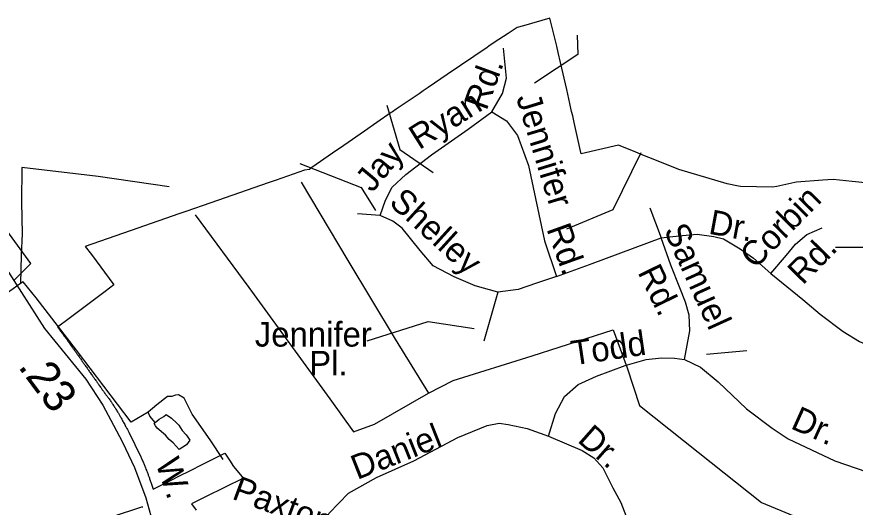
# Model space of a CAD drawing. Extents: x 2315291 to 2336543, y 597177 to 615230.
# Drawn here: x 2318553 to 2321792, y 600720 to 602614 of the extents above; entities that cross this region are included whole.
import ezdxf

# ---------------------------------------------------------------- set-up
doc = ezdxf.new("R2010")
doc.units = 0
for name, color, linetype in [('Exist Boundary Political City Limit New', 7, 'Continuous'), ('Exist Boundary Political Urban Extension UEB', 7, 'Continuous'), ('Exist Hydrographic Misc Water Feature', 7, 'Continuous'), ('Exist Road Non-System Type 51', 7, 'Continuous'), ('Exist Road Non-System Type 51 Label', 7, 'Continuous'), ('Exist Road Secondary Mileage Hundredths English Label', 7, 'Continuous'), ('Exist Road Secondary Type 51 Attributed', 7, 'Continuous'), ('Exist Road Secondary Type 51 Label', 7, 'Continuous'), ('Map Preparation Boundary City Limit Buffer Line', 7, 'Continuous')]:
    doc.layers.add(name, color=color, linetype=linetype)

msp = doc.modelspace()

# ---------------------------------------------------------------- linework, layer by layer
at = {"layer": 'Exist Boundary Political City Limit New'}
for points in [[(2320677.5, 602333.2), (2320653.5, 602437), (2320644.2, 602476), (2320638.8, 602500), (2320631.5, 602530.6), (2320612.8, 602608.9), (2320510, 602579.2), (2320486, 602572.2), (2320451.5, 602549.4), (2320397.5, 602513.8), (2320377, 602500), (2320370.2, 602495.4), (2320216.2, 602391.1), (2320142.2, 602340.3), (2320123.2, 602327.2), (2320107.5, 602316.6), (2320018.8, 602256.4), (2320005.2, 602247.1), (2320000, 602243.4), (2319944.2, 602204.8), (2319896, 602171.5), (2319816.2, 602116.2), (2319773.2, 602086.5), (2319693.5, 602031.3), (2319683.8, 602024.5), (2319664.2, 602021.1), (2319555.2, 601983.2), (2319524.8, 601972.6), (2319302.8, 601895.4), (2319206.2, 601861.8), (2319179.5, 601852.5), (2319021, 601797.4), (2318817.8, 601726.8), (2318841.5, 601695.1), (2318928.5, 601578.3), (2318894.8, 601553.1), (2318755.8, 601448.9), (2318711.2, 601415.7), (2318712, 601414.7), (2318713.8, 601412.2), (2318715.5, 601409.9), (2318718, 601406.6), (2318720.2, 601403.4), (2318722.8, 601400.2), (2318725, 601396.9), (2318727.5, 601393.8), (2318729.8, 601390.5), (2318732.2, 601387.2), (2318734.5, 601384), (2318736.8, 601380.8), (2318738.5, 601378.4), (2318740.2, 601375.9), (2318742.8, 601372.7), (2318745, 601369.4), (2318747.5, 601366.2), (2318749.2, 601363.8), (2318751, 601361.3), (2318752.8, 601358.9), (2318754.5, 601356.4), (2318756.8, 601353.2), (2318761.2, 601346.7), (2318763.8, 601343.4), (2318768.2, 601336.9), (2318770, 601334.5), (2318771.8, 601332), (2318773.5, 601329.6), (2318775.2, 601327.1), (2318777, 601324.7), (2318778.8, 601322.2), (2318780.5, 601319.8), (2318781.2, 601318.8), (2318781.8, 601318.2), (2318782.5, 601316.9), (2318784, 601314.9), (2318785.8, 601312.5), (2318787.5, 601310), (2318789.2, 601307.6), (2318791.5, 601304.3), (2318793.8, 601301), (2318795.5, 601298.6), (2318797.2, 601296.1), (2318799, 601293.7), (2318800.8, 601291.2), (2318803, 601288), (2318804.8, 601285.5), (2318806.5, 601283.1), (2318808.8, 601279.8), (2318810.5, 601277.3), (2318812.2, 601274.9), (2318814, 601272.4), (2318815.8, 601270), (2318818, 601266.8), (2318820.2, 601263.4), (2318822.5, 601260.2), (2318825, 601256.9), (2318827.2, 601253.6), (2318829, 601251.2), (2318830.8, 601248.8)], [(2321905.8, 601965.2), (2321779.8, 601978), (2321707, 601985.4), (2321686.5, 601983.8), (2321666, 601982.3), (2321565, 601974.6), (2321558, 601974.1), (2321488.5, 601958.8), (2321472, 601955.1), (2321348, 601957.8), (2321341, 601959.1), (2321297.5, 601968.4), (2321109.8, 602023.9), (2321018.2, 602060.7), (2320971.2, 602079.6), (2320943.8, 602090.6), (2320876.8, 602117.6), (2320733.5, 602083.8), (2320732.5, 602089.1), (2320706.2, 602205), (2320700.5, 602230.9), (2320696.5, 602248.5), (2320689.8, 602278.9), (2320677.5, 602333.2)], [(2318830.8, 601248.8), (2318833, 601245.5), (2318834.8, 601243.1)], [(2318834.8, 601243.1), (2318836.5, 601240.6), (2318841, 601234.1), (2318843.5, 601230.8), (2318845.8, 601227.5), (2318847.5, 601225.1), (2318849.2, 601222.6), (2318851, 601220.2), (2318852.5, 601217.7), (2318854.2, 601215.2), (2318856, 601212.8), (2318858.5, 601209.6), (2318860.8, 601206.2), (2318862.5, 601203.8), (2318864.2, 601201.4), (2318866, 601198.9), (2318867.8, 601196.5), (2318870, 601193.2), (2318872.2, 601189.9), (2318874.5, 601186.7), (2318877, 601183.4), (2318879.2, 601180.2), (2318883.8, 601173.7), (2318886.2, 601170.4), (2318888, 601167.9), (2318889.8, 601165.5), (2318892, 601162.2), (2318894.2, 601159.1), (2318896.2, 601156.6), (2318898, 601154.2), (2318900.5, 601151.1), (2318902.2, 601148.7), (2318904, 601146.3), (2318906.5, 601143.1), (2318908.2, 601140.8), (2318910, 601138.3), (2318912.5, 601135.1), (2318914.8, 601131.8), (2318917, 601128.5), (2318919.2, 601125.2), (2318921, 601122.7), (2318922.2, 601120.6), (2318923, 601119.4), (2318924.8, 601116.9), (2318927, 601113.2), (2318929.2, 601110), (2318931.2, 601106.8), (2318933, 601104.2), (2318934.5, 601101.4), (2318936.5, 601098.3), (2318938.8, 601094.9), (2318940.5, 601091.9), (2318942.8, 601088.1), (2318944.2, 601085.4), (2318945.8, 601082.9), (2318947.2, 601080.2), (2318948.8, 601077.7), (2318950.2, 601075.1), (2318951.8, 601072.5), (2318953.2, 601069.9), (2318954.8, 601067.1), (2318956.8, 601063.8), (2318958.8, 601060.2), (2318960.5, 601056.8), (2318962.2, 601053.5), (2318964.5, 601049.8), (2318966.2, 601046.4), (2318968.2, 601042.7), (2318970.2, 601039.2), (2318972, 601035.9), (2318974, 601032.1), (2318976, 601028.6), (2318977.2, 601026), (2318978.8, 601023.5), (2318980.5, 601019.8), (2318982, 601017.2), (2318983.2, 601014.5), (2318985, 601011.6), (2318985.8, 601009.9), (2319032, 600914.8), (2319033.5, 600911.4), (2319035, 600907.9), (2319036.2, 600904.9), (2319037.8, 600901.9), (2319039.2, 600898.5), (2319041, 600894.7), (2319042.5, 600891.2), (2319043.8, 600888.4), (2319045, 600885.4), (2319046.5, 600882), (2319048, 600878.3), (2319049.2, 600875.6), (2319051, 600871.3), (2319052.5, 600867.2), (2319054.2, 600863.4), (2319054.5, 600862.5), (2319054.8, 600861.6), (2319056, 600858.9)], [(2319056, 600858.9), (2319057, 600856.1), (2319058.2, 600852.4), (2319059.5, 600849.5), (2319060.5, 600846.7), (2319061.5, 600843.8), (2319062.5, 600841), (2319063.5, 600838.2), (2319064.5, 600835.4), (2319065.5, 600832.5), (2319066.5, 600829.7), (2319067.8, 600825.7), (2319068.2, 600824.6), (2319069, 600822.1), (2319070, 600819.3), (2319071, 600816.4), (2319072.2, 600812.6), (2319073.2, 600809.2), (2319074.8, 600805.1), (2319076, 600801.1), (2319077.2, 600797.3), (2319078.5, 600793.6), (2319079.8, 600789.8), (2319155.2, 600827.4), (2319179.2, 600839.6), (2319182, 600841.1), (2319221.8, 600860.9), (2319271.5, 600885.9), (2319356.8, 600928.6), (2319375.2, 600900.9), (2319391, 600877.7), (2319424.2, 600837.7), (2319428.8, 600832.6), (2319281.8, 600759.5), (2319241.2, 600739.5), (2319228.8, 600733.2), (2319246.5, 600708.2)], [(2319039.5, 600718.5), (2319038.8, 600721.7), (2318179, 600438.4)]]:
    msp.add_lwpolyline(points, dxfattribs=at)
at = {"layer": 'Exist Boundary Political Urban Extension UEB'}
msp.add_lwpolyline([(2318542.1, 601594.9), (2318607.6, 601660.5), (2318494.4, 601816.2), (2318437.7, 601929.5), (2318395.3, 602099.4), (2318366.9, 602297.6), (2318423.6, 602453.3), (2318451.9, 602665.7), (2318494.4, 602906.3), (2318466, 603090.4), (2318423.6, 603175.3), (2318692.6, 603345.2), (2318735.1, 603387.7), (2318848.4, 603600.1), (2319238.3, 604375.7)], dxfattribs=at)
at = {"layer": 'Exist Hydrographic Misc Water Feature'}
for points in [[(2319141.7, 601957.6), (2318867.4, 601996.5), (2318573.5, 602031.3), (2318572.3, 601897.3), (2318573.7, 601775.4), (2318570.9, 601693.6), (2318568.2, 601583.2)], [(2319651.3, 601975), (2319832.1, 601672.8), (2320015.5, 601369.1), (2320143.8, 601160.7)], [(2319243, 601848.6), (2319449.7, 601568.9), (2319762, 601138.3), (2319853.5, 601011.4), (2319935.3, 601040.5), (2320074.1, 601119.7), (2320143.8, 601160.7)], [(2318568.2, 601583.2), (2318540.1, 601563.1), (2318496.4, 601532.8), (2318492.3, 601528.5)], [(2319060.9, 601086.9), (2318995.5, 601048.5), (2318784.5, 601326), (2318628.7, 601528.3), (2318577.6, 601589.5), (2318568.2, 601583.2)], [(2320143.8, 601160.7), (2320239.2, 601209.6), (2320544.1, 601304.9), (2320856.8, 601404.2), (2320910.3, 601258.7), (2320957.9, 601113.2), (2321185.3, 600931.8), (2321429.5, 600738.5), (2321842.9, 600567.2), (2322346.9, 600362.8), (2322643, 600741.7), (2323035.1, 601251.6), (2323257.7, 601549.8)], [(2319350.7, 600904.2), (2319299.8, 600979.6), (2319230.9, 601078.8), (2319200, 601140.6), (2319178, 601154), (2319166.3, 601152.2), (2319152.4, 601147.8), (2319136.2, 601147.8), (2319094.8, 601115.5), (2319060.9, 601086.9)], [(2319087.6, 601047.2), (2319067.3, 601070.9), (2319060.9, 601086.9)], [(2319087.6, 601047.2), (2319103.2, 601059.4), (2319121, 601069.7), (2319130.9, 601077.6), (2319151.6, 601063.9), (2319171.7, 601044.3), (2319179.3, 601036.2), (2319191.8, 601016.5), (2319207.8, 600998.7), (2319214.1, 600990.8), (2319221.9, 600978.7), (2319208.4, 600960.5), (2319180.7, 600942.3), (2319158.1, 600968), (2319141.7, 600981.9), (2319127.8, 600997.8), (2319095.8, 601025.3), (2319089.4, 601033.5), (2319083.5, 601043.3), (2319087.6, 601047.2)]]:
    msp.add_lwpolyline(points, dxfattribs=at)
at = {"layer": 'Exist Road Non-System Type 51'}
for p, q in [((2320998.9, 601876.1), (2321042.1, 601759.8)), ((2319956.7, 601846.7), (2319869.5, 601852.8)), ((2320410.9, 601550.5), (2320357.2, 601360.7))]:
    msp.add_line(p, q, dxfattribs=at)
for points in [[(2320388.6, 602246.4), (2320429.1, 602317.4), (2320445.3, 602376.3), (2320433.2, 602491.9)], [(2319956.7, 601846.7), (2319977, 601905.6), (2320003.3, 601956.3), (2320056, 602005), (2320155.4, 602080.1), (2320297.3, 602179.5), (2320388.6, 602246.4)], [(2320388.6, 602246.4), (2320445.3, 602211.9), (2320487.9, 602155.1), (2320529.8, 602039.8), (2320556.9, 601911.3), (2320592, 601749), (2320638, 601611)], [(2320410.9, 601550.5), (2320323.7, 601574.9), (2320242.6, 601609.4), (2320161.5, 601652), (2320110.8, 601710.8), (2320041.8, 601798), (2320005.4, 601824.4), (2319956.7, 601846.7)], [(2321465.2, 601622.5), (2321526.1, 601693.5), (2321560.5, 601736.2), (2321605.1, 601772.7), (2321663.9, 601799.1)], [(2321042.1, 601759.8), (2321086.7, 601765.2), (2321124.6, 601768.6), (2321181.4, 601774.7), (2321246.2, 601764.6), (2321282.7, 601756.4), (2321347.6, 601717.9), (2321398.3, 601681.4), (2321465.2, 601622.5)], [(2320638, 601611), (2320765, 601657), (2320886.7, 601701.7), (2321042.1, 601759.8)], [(2321132.7, 601290.8), (2321153, 601400.4), (2321150.9, 601461.2), (2321136.8, 601512), (2321114.4, 601566.7), (2321080, 601654), (2321042.1, 601759.8)], [(2320638, 601611), (2320560.9, 601585), (2320489.9, 601560.7), (2320410.9, 601550.5)], [(2321465.2, 601622.5), (2321588.9, 601522.1), (2321655.8, 601465.3), (2321745, 601398.3), (2321807.9, 601359.8), (2321868.7, 601333.4), (2321945.8, 601303), (2322018.8, 601268.5), (2322085.7, 601219.8), (2322132.3, 601163), (2322162.7, 601116.3), (2322174.9, 601070.7), (2322187, 601028.1), (2322205.3, 600951), (2322223.5, 600871.9)], [(2320607.6, 600993.6), (2320633.9, 601081.8), (2320668.4, 601146.8), (2320721.1, 601193.4), (2320792.1, 601225.9), (2320903.6, 601266.5), (2320984.7, 601290.8), (2321043.5, 601296.9), (2321094.2, 601294.9), (2321132.7, 601290.8)], [(2321132.7, 601290.8), (2321193.5, 601260.4), (2321262.5, 601203.6), (2321372, 601100.1), (2321471.3, 601025), (2321532.1, 600984.5), (2321712.6, 600899.2), (2321836.3, 600856.6), (2321927.5, 600837.4), (2321996.5, 600835.3), (2322077.6, 600841.4), (2322156.6, 600855.6), (2322199.2, 600865.8), (2322223.5, 600871.9)], [(2319717.4, 600611.1), (2319735.7, 600651.7), (2319760, 600696.4), (2319835, 600773.5), (2319942.5, 600834.3), (2320086.5, 600899.2), (2320256.8, 600988.5), (2320370.3, 601035.2), (2320417, 601044.3), (2320451.4, 601039.2), (2320524.4, 601024), (2320607.6, 600993.6)], [(2320607.6, 600993.6), (2320737.3, 600938.8), (2320781.9, 600910.4), (2320816.4, 600871.9), (2320855.3, 600794.2), (2320885.9, 600738.4), (2320929, 600626.9), (2320956.3, 600564.5)]]:
    msp.add_lwpolyline(points, dxfattribs=at)
at = {"layer": 'Exist Road Non-System Type 51 Label'}
for points in [[(2320718.4, 602542.6), (2320720.5, 602468.1), (2320552.4, 602357.3)], [(2319982.4, 602272.1), (2320033.5, 602101.7), (2320161.2, 602012.2)], [(2320963.6, 602088.1), (2320855.6, 601868.2), (2320676.9, 601793.7)], [(2319646.5, 602047.6), (2319883.9, 601954.7), (2319938.4, 601865.8)], [(2322058.3, 601801.1), (2321928, 601722.9), (2321715.7, 601722.9)], [(2319907.1, 601362), (2320141.7, 601436.5), (2320320.4, 601410.4)], [(2321373.2, 601324.2), (2321216.8, 601309.3)]]:
    msp.add_lwpolyline(points, dxfattribs=at)
at = {"layer": 'Exist Road Secondary Type 51 Attributed'}
msp.add_lwpolyline([(2318498.2, 601663.5), (2318542.1, 601594.9), (2318660.7, 601409.7), (2318820.7, 601214.7), (2318885.4, 601114.3), (2318927.3, 601036.8), (2318961.6, 600970.7), (2319008.2, 600873.1), (2319051.3, 600756.2), (2319090.9, 600617.6), (2319100.2, 600571.4), (2319144.5, 600351.3), (2319197.8, 600111.2), (2319253, 599927.3), (2319300.4, 599837.8), (2319321.6, 599790.1), (2319355.9, 599740.5), (2319403.5, 599670), (2319477.8, 599578.5), (2319616.8, 599450.8), (2319723.5, 599353.6), (2319780.6, 599306), (2319817.5, 599280.1), (2319875.9, 599227.8)], dxfattribs=at)
at = {"layer": 'Map Preparation Boundary City Limit Buffer Line'}
for points in [[(2320677.5, 602333.2), (2320653.5, 602437), (2320644.2, 602476), (2320638.8, 602500), (2320631.5, 602530.6), (2320612.8, 602608.9), (2320510, 602579.2), (2320486, 602572.2), (2320451.5, 602549.4), (2320397.5, 602513.8), (2320377, 602500), (2320370.2, 602495.4), (2320216.2, 602391.1), (2320142.2, 602340.3), (2320123.2, 602327.2), (2320107.5, 602316.6), (2320018.8, 602256.4), (2320005.2, 602247.1), (2320000, 602243.4), (2319944.2, 602204.8), (2319896, 602171.5), (2319816.2, 602116.2), (2319773.2, 602086.5), (2319693.5, 602031.3), (2319683.8, 602024.5), (2319664.2, 602021.1), (2319555.2, 601983.2), (2319524.8, 601972.6), (2319302.8, 601895.4), (2319206.2, 601861.8), (2319179.5, 601852.5), (2319021, 601797.4), (2318817.8, 601726.8), (2318841.5, 601695.1), (2318928.5, 601578.3), (2318894.8, 601553.1), (2318755.8, 601448.9), (2318711.2, 601415.7), (2318712, 601414.7), (2318713.8, 601412.2), (2318715.5, 601409.9), (2318718, 601406.6), (2318720.2, 601403.4), (2318722.8, 601400.2), (2318725, 601396.9), (2318727.5, 601393.8), (2318729.8, 601390.5), (2318732.2, 601387.2), (2318734.5, 601384), (2318736.8, 601380.8), (2318738.5, 601378.4), (2318740.2, 601375.9), (2318742.8, 601372.7), (2318745, 601369.4), (2318747.5, 601366.2), (2318749.2, 601363.8), (2318751, 601361.3), (2318752.8, 601358.9), (2318754.5, 601356.4), (2318756.8, 601353.2), (2318761.2, 601346.7), (2318763.8, 601343.4), (2318768.2, 601336.9), (2318770, 601334.5), (2318771.8, 601332), (2318773.5, 601329.6), (2318775.2, 601327.1), (2318777, 601324.7), (2318778.8, 601322.2), (2318780.5, 601319.8), (2318781.2, 601318.8), (2318781.8, 601318.2), (2318782.5, 601316.9), (2318784, 601314.9), (2318785.8, 601312.5), (2318787.5, 601310), (2318789.2, 601307.6), (2318791.5, 601304.3), (2318793.8, 601301), (2318795.5, 601298.6), (2318797.2, 601296.1), (2318799, 601293.7), (2318800.8, 601291.2), (2318803, 601288), (2318804.8, 601285.5), (2318806.5, 601283.1), (2318808.8, 601279.8), (2318810.5, 601277.3), (2318812.2, 601274.9), (2318814, 601272.4), (2318815.8, 601270), (2318818, 601266.8), (2318820.2, 601263.4), (2318822.5, 601260.2), (2318825, 601256.9), (2318827.2, 601253.6), (2318829, 601251.2), (2318830.8, 601248.8)], [(2321905.8, 601965.2), (2321779.8, 601978), (2321707, 601985.4), (2321686.5, 601983.8), (2321666, 601982.3), (2321565, 601974.6), (2321558, 601974.1), (2321488.5, 601958.8), (2321472, 601955.1), (2321348, 601957.8), (2321341, 601959.1), (2321297.5, 601968.4), (2321109.8, 602023.9), (2321018.2, 602060.7), (2320971.2, 602079.6), (2320943.8, 602090.6), (2320876.8, 602117.6), (2320733.5, 602083.8), (2320732.5, 602089.1), (2320706.2, 602205), (2320700.5, 602230.9), (2320696.5, 602248.5), (2320689.8, 602278.9), (2320677.5, 602333.2)], [(2318830.8, 601248.8), (2318833, 601245.5), (2318834.8, 601243.1)], [(2318834.8, 601243.1), (2318836.5, 601240.6), (2318841, 601234.1), (2318843.5, 601230.8), (2318845.8, 601227.5), (2318847.5, 601225.1), (2318849.2, 601222.6), (2318851, 601220.2), (2318852.5, 601217.7), (2318854.2, 601215.2), (2318856, 601212.8), (2318858.5, 601209.6), (2318860.8, 601206.2), (2318862.5, 601203.8), (2318864.2, 601201.4), (2318866, 601198.9), (2318867.8, 601196.5), (2318870, 601193.2), (2318872.2, 601189.9), (2318874.5, 601186.7), (2318877, 601183.4), (2318879.2, 601180.2), (2318883.8, 601173.7), (2318886.2, 601170.4), (2318888, 601167.9), (2318889.8, 601165.5), (2318892, 601162.2), (2318894.2, 601159.1), (2318896.2, 601156.6), (2318898, 601154.2), (2318900.5, 601151.1), (2318902.2, 601148.7), (2318904, 601146.3), (2318906.5, 601143.1), (2318908.2, 601140.8), (2318910, 601138.3), (2318912.5, 601135.1), (2318914.8, 601131.8), (2318917, 601128.5), (2318919.2, 601125.2), (2318921, 601122.7), (2318922.2, 601120.6), (2318923, 601119.4), (2318924.8, 601116.9), (2318927, 601113.2), (2318929.2, 601110), (2318931.2, 601106.8), (2318933, 601104.2), (2318934.5, 601101.4), (2318936.5, 601098.3), (2318938.8, 601094.9), (2318940.5, 601091.9), (2318942.8, 601088.1), (2318944.2, 601085.4), (2318945.8, 601082.9), (2318947.2, 601080.2), (2318948.8, 601077.7), (2318950.2, 601075.1), (2318951.8, 601072.5), (2318953.2, 601069.9), (2318954.8, 601067.1), (2318956.8, 601063.8), (2318958.8, 601060.2), (2318960.5, 601056.8), (2318962.2, 601053.5), (2318964.5, 601049.8), (2318966.2, 601046.4), (2318968.2, 601042.7), (2318970.2, 601039.2), (2318972, 601035.9), (2318974, 601032.1), (2318976, 601028.6), (2318977.2, 601026), (2318978.8, 601023.5), (2318980.5, 601019.8), (2318982, 601017.2), (2318983.2, 601014.5), (2318985, 601011.6), (2318985.8, 601009.9), (2319032, 600914.8), (2319033.5, 600911.4), (2319035, 600907.9), (2319036.2, 600904.9), (2319037.8, 600901.9), (2319039.2, 600898.5), (2319041, 600894.7), (2319042.5, 600891.2), (2319043.8, 600888.4), (2319045, 600885.4), (2319046.5, 600882), (2319048, 600878.3), (2319049.2, 600875.6), (2319051, 600871.3), (2319052.5, 600867.2), (2319054.2, 600863.4), (2319054.5, 600862.5), (2319054.8, 600861.6), (2319056, 600858.9)], [(2319056, 600858.9), (2319057, 600856.1), (2319058.2, 600852.4), (2319059.5, 600849.5), (2319060.5, 600846.7), (2319061.5, 600843.8), (2319062.5, 600841), (2319063.5, 600838.2), (2319064.5, 600835.4), (2319065.5, 600832.5), (2319066.5, 600829.7), (2319067.8, 600825.7), (2319068.2, 600824.6), (2319069, 600822.1), (2319070, 600819.3), (2319071, 600816.4), (2319072.2, 600812.6), (2319073.2, 600809.2), (2319074.8, 600805.1), (2319076, 600801.1), (2319077.2, 600797.3), (2319078.5, 600793.6), (2319079.8, 600789.8), (2319155.2, 600827.4), (2319179.2, 600839.6), (2319182, 600841.1), (2319221.8, 600860.9), (2319271.5, 600885.9), (2319356.8, 600928.6), (2319375.2, 600900.9), (2319391, 600877.7), (2319424.2, 600837.7), (2319428.8, 600832.6), (2319281.8, 600759.5), (2319241.2, 600739.5), (2319228.8, 600733.2), (2319246.5, 600708.2)], [(2319039.5, 600718.5), (2319038.8, 600721.7), (2318179, 600438.4)]]:
    msp.add_lwpolyline(points, dxfattribs=at)

# ---------------------------------------------------------------- texts
at = {"layer": 'Exist Road Non-System Type 51 Label'}
for s, rotation, p in [('Rd.', 69.9218, (2320367.6, 602248.3)), ('Ryan', 32.2245, (2320107.5, 602098.1)), ('Jennifer', 287.0543, (2320481.4, 602301.9)), ('Jay', 50.1434, (2319926, 601931.6)), ('Shelley', 317.6564, (2319987, 601891)), ('Corbin', 45.5024, (2321404.9, 601636.5)), ('Dr.', 349.4776, (2321221.9, 601776.5)), ('Rd.', 289.7261, (2320598.3, 601795)), ('Samuel', 294.4519, (2321051.1, 601789.3)), ('Rd.', 45.5024, (2321589.1, 601574.6)), ('Rd.', 296.181, (2320949.7, 601627.5)), ('Todd', 8.4189, (2320701.8, 601267.2)), ('Dr.', 335.793, (2321538.1, 601025.9)), ('Daniel', 21.5918, (2319868.1, 600824.7)), ('Dr.', 318.5346, (2320715.1, 600975)), ('Paxton', 339.5208, (2319380.5, 600753.5))]:
    msp.add_text(s, height=95, rotation=rotation, dxfattribs=at).set_placement(p)
for s, p in [('Jennifer', (2319472.8, 601340)), ('Pl.', (2319682.8, 601228.7))]:
    msp.add_text(s, height=95, dxfattribs=at).set_placement(p)
at = {"layer": 'Exist Road Secondary Mileage Hundredths English Label'}
msp.add_text('.23', height=125, rotation=306.6156, dxfattribs=at).set_placement((2318555.7, 601262.5))
at = {"layer": 'Exist Road Secondary Type 51 Label'}
msp.add_text('W.', height=95, rotation=288.7014, dxfattribs=at).set_placement((2319088.5, 600891.5))

doc.saveas('drawing.dxf')
